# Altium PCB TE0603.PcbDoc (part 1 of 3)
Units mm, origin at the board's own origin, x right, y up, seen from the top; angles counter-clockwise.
Board outline 115 x 70 mm, 4 copper layers (L 01 (Top), L 02, L 03, L 04 (Bot)), stack 1.564 mm thick; 86 components, 166 nets, 587 pads, 211 vias.
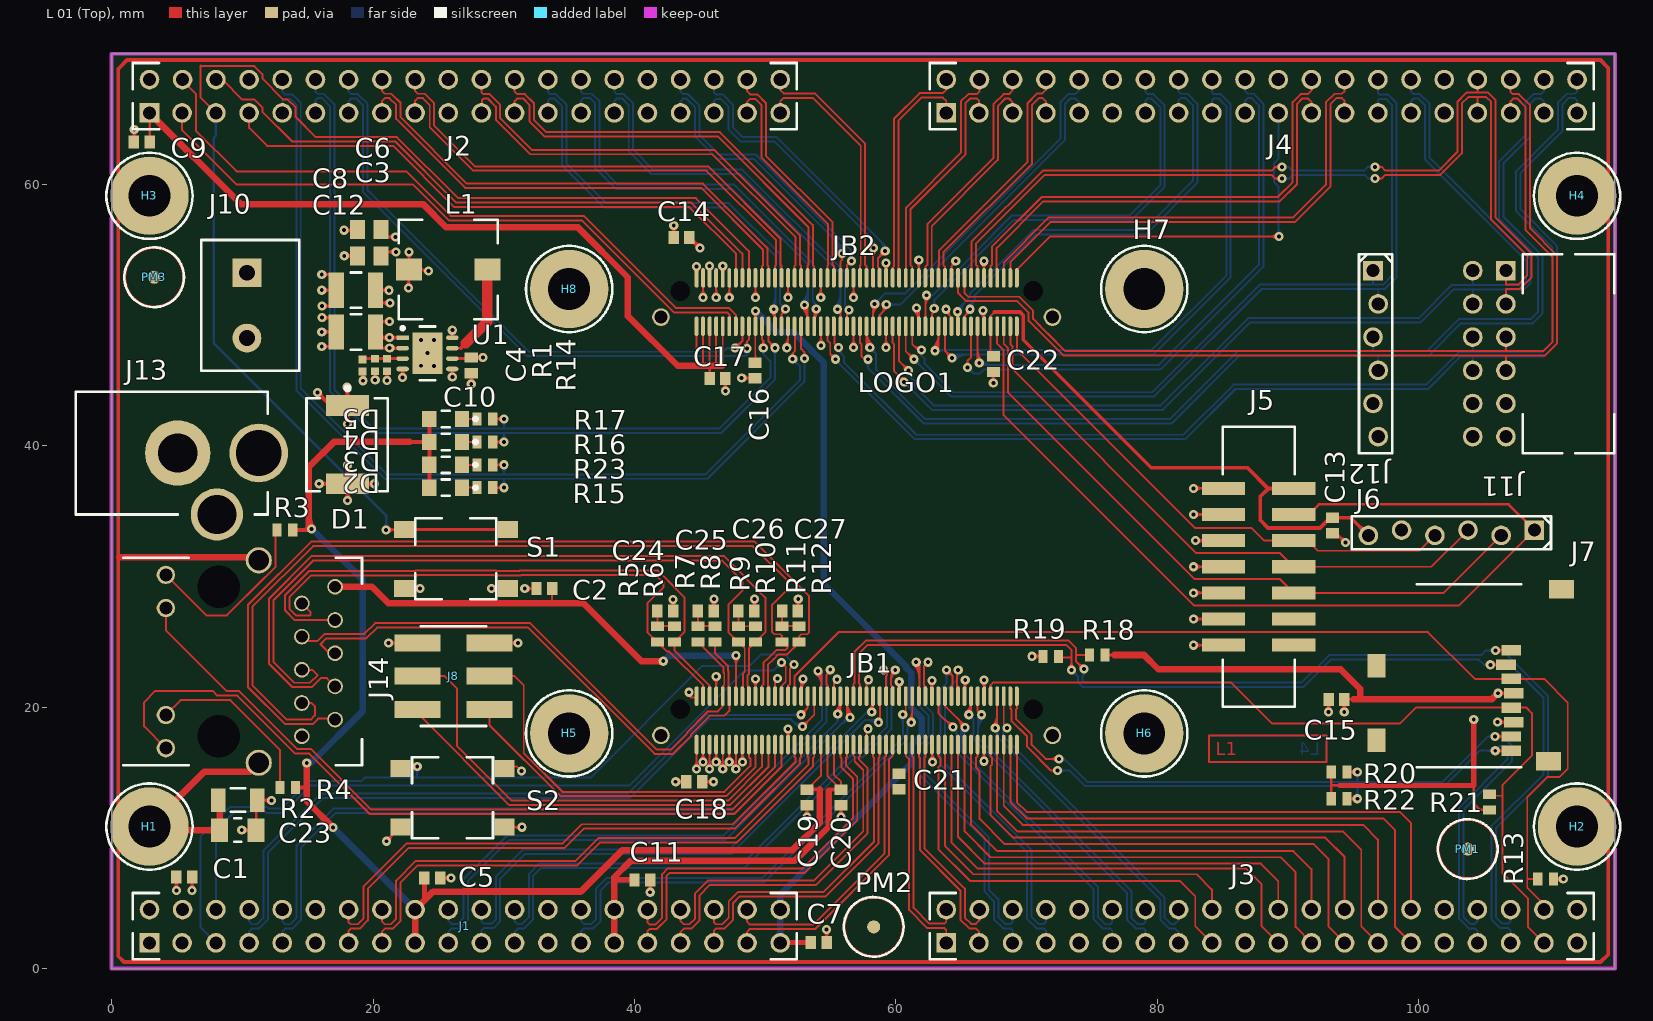
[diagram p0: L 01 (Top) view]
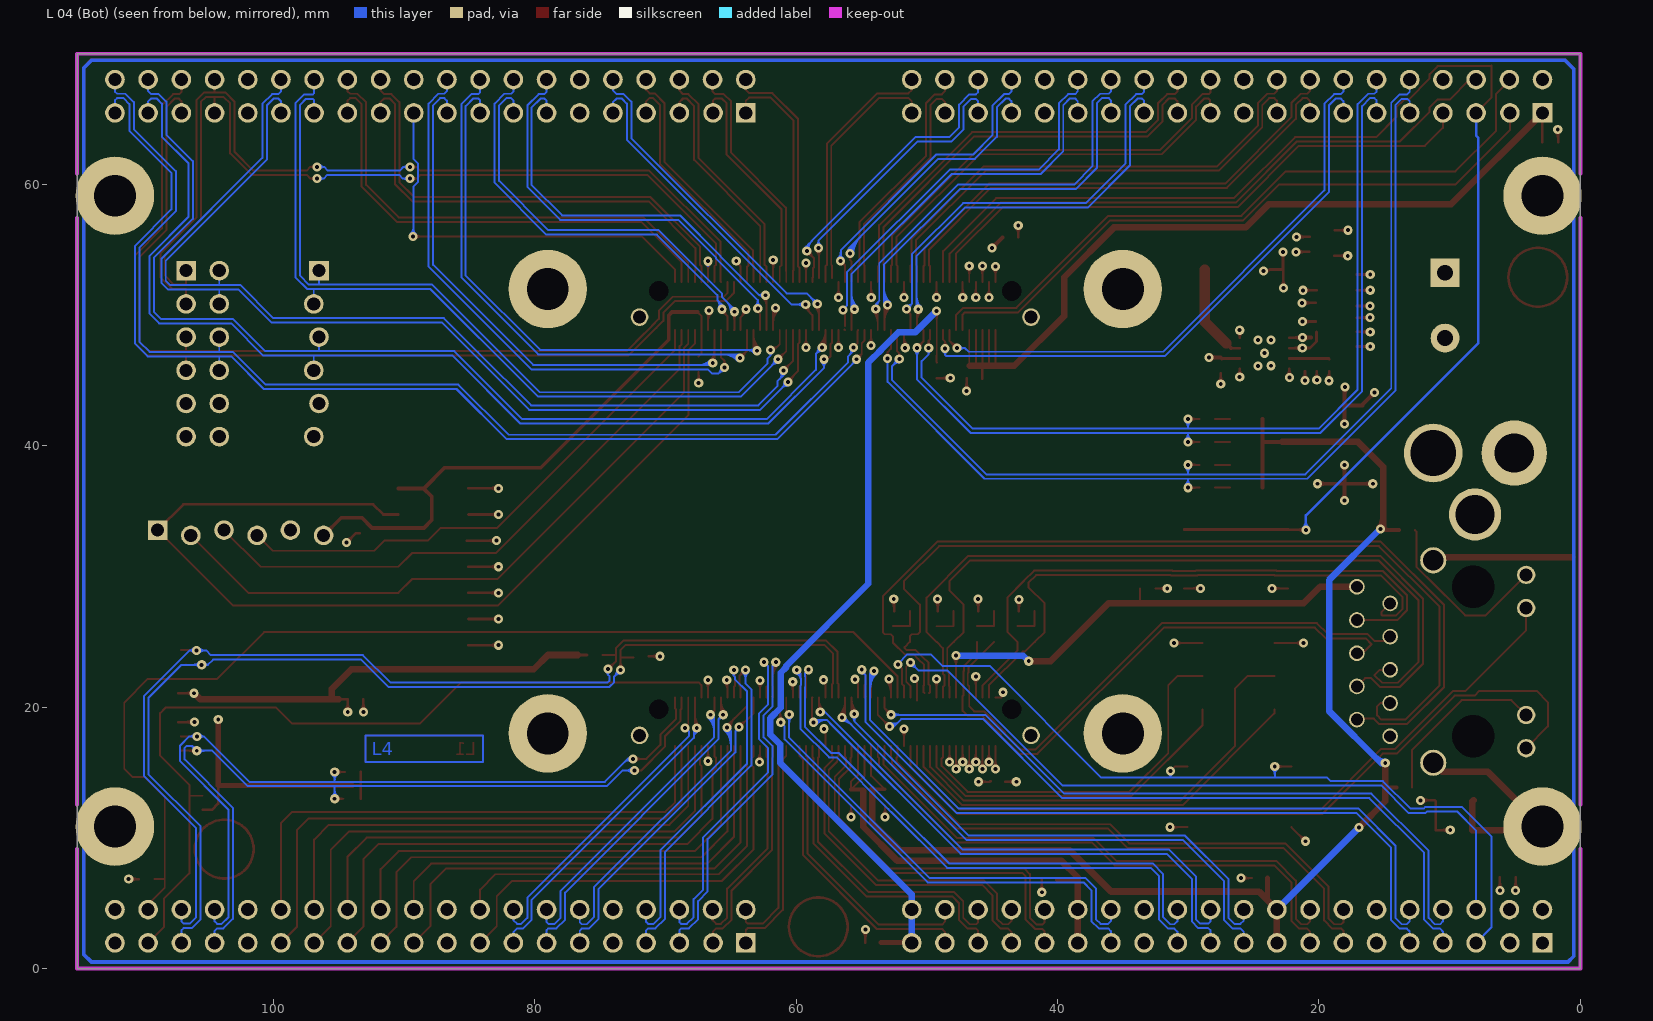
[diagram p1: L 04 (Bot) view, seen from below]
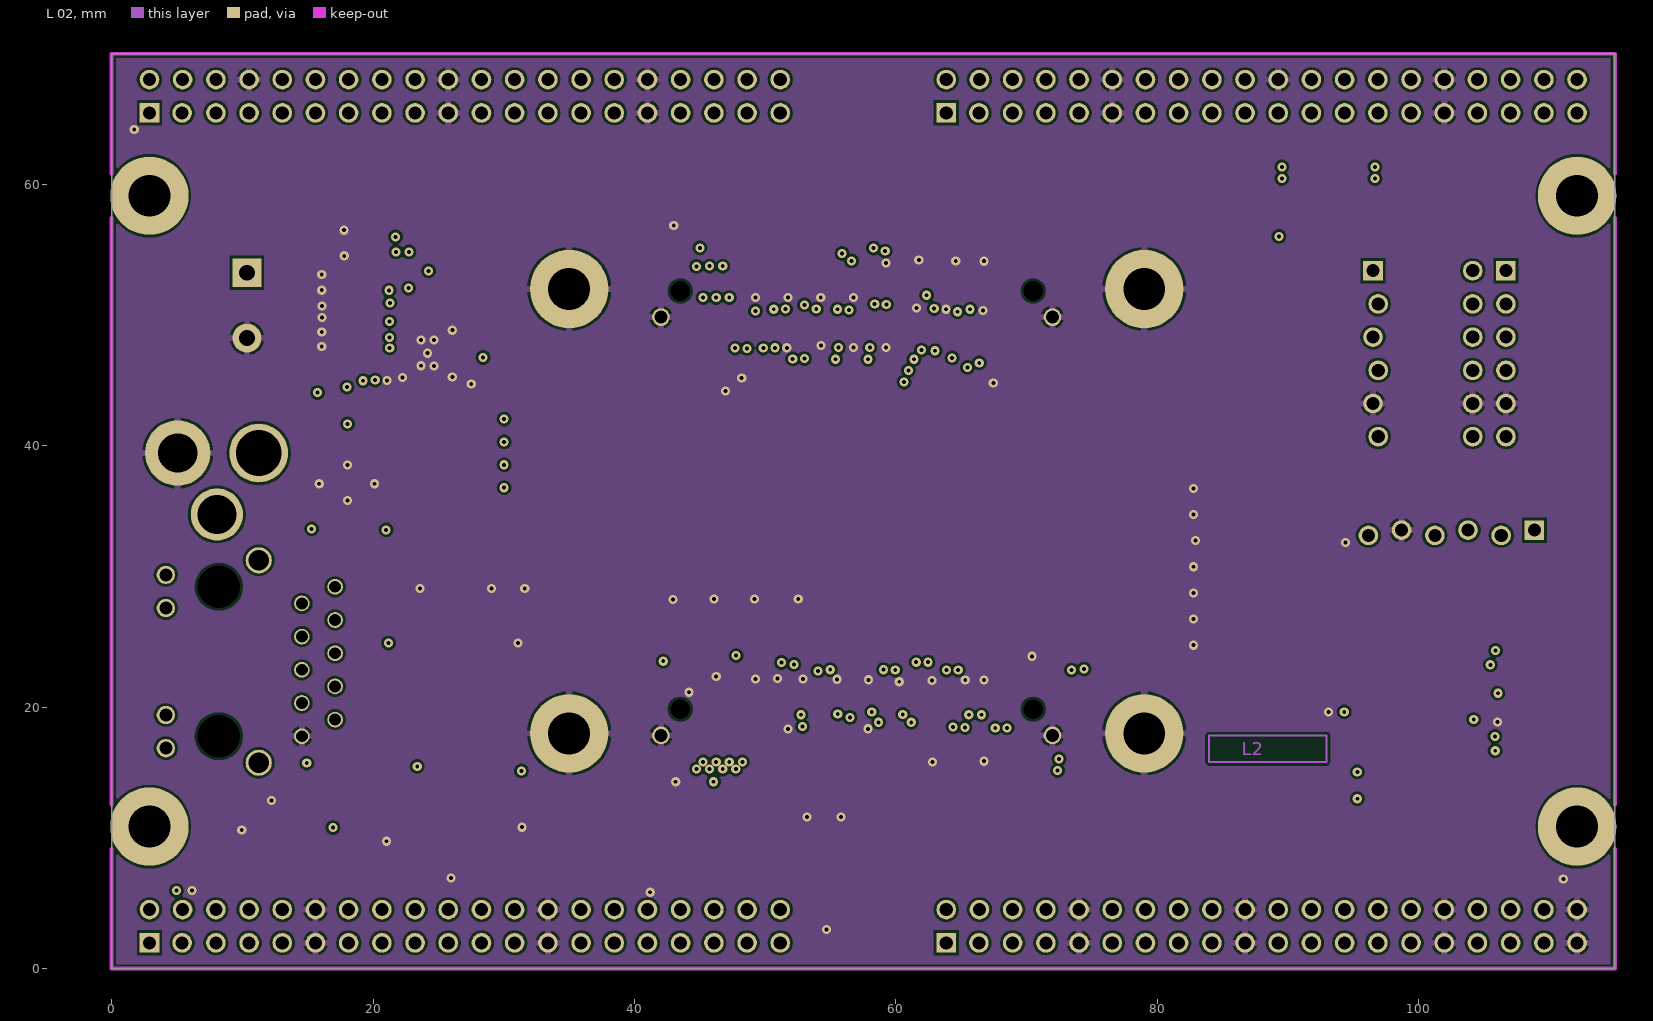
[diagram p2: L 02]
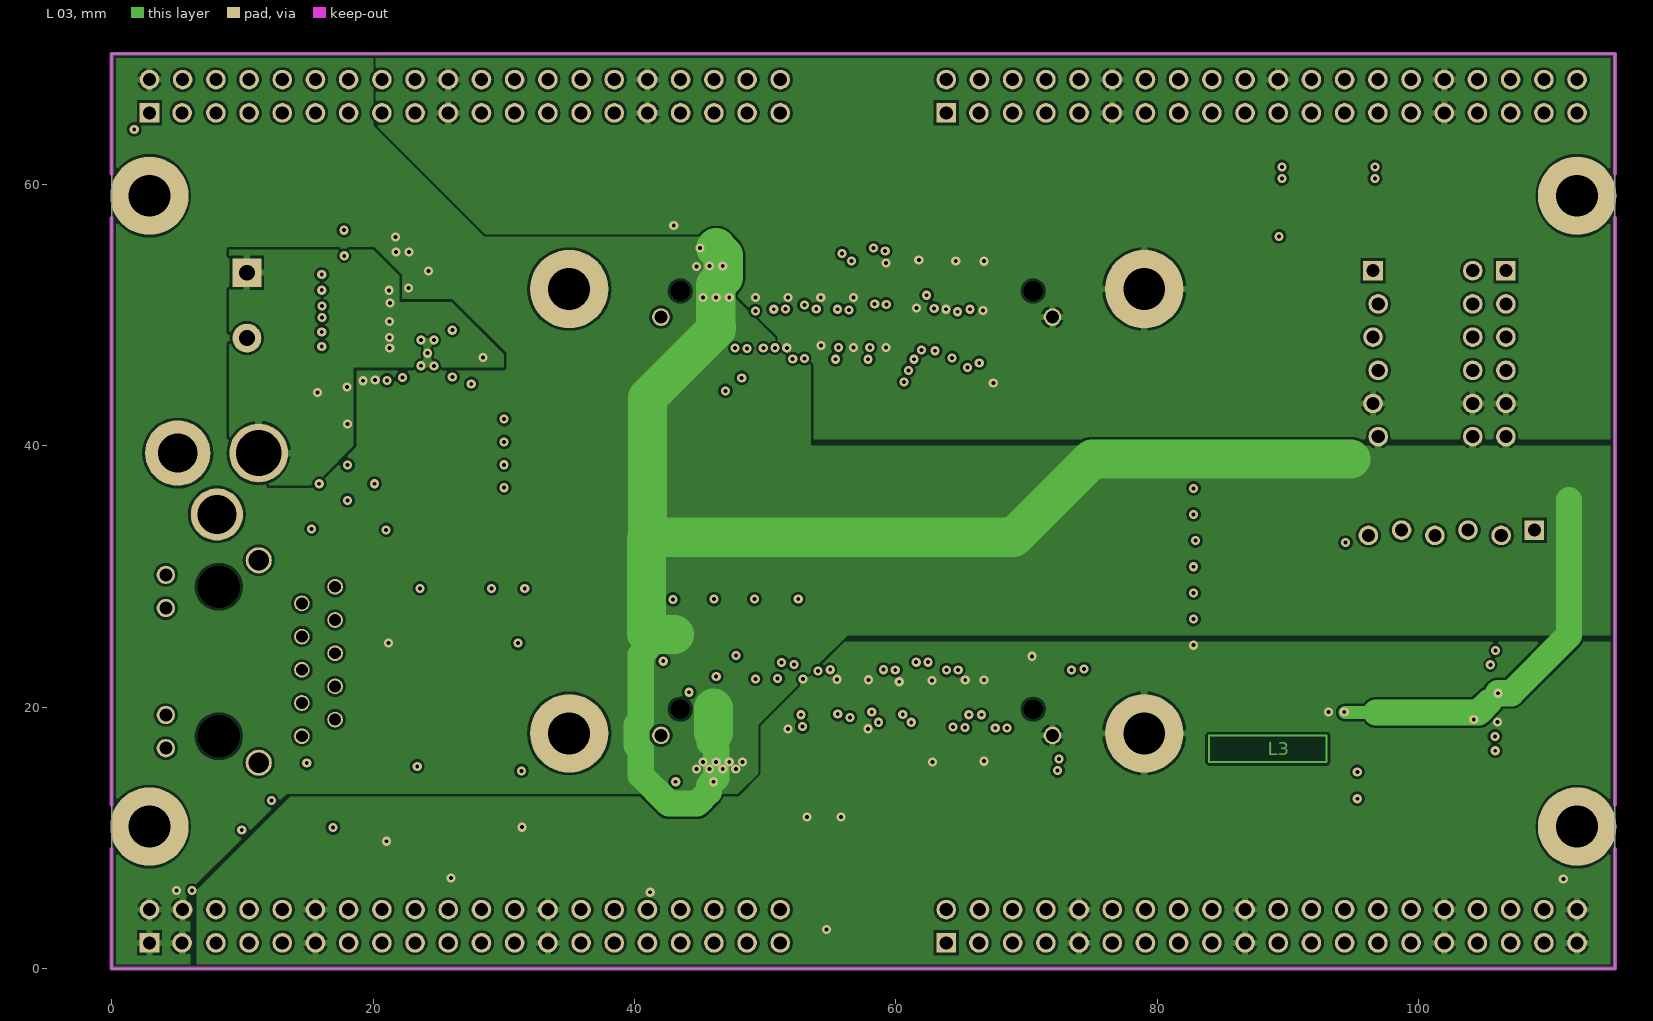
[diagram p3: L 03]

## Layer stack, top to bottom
L 01 (Top): signal copper 0.05
Dielectric: core 0.134, FR-4, Dk 4.8
L 02: signal copper 0.033
Dielectric: prepreg 1.13, FR-4, Dk 4.8
L 03: signal copper 0.033
Dielectric: core 0.134, FR-4, Dk 4.8
L 04 (Bot): signal copper 0.05

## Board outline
0.001,-0.001 0.001,69.999 115.001,69.999 115.001,-0.001

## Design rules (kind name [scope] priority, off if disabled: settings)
Clearance Clearance_Polygon [(InPolygon)] p1: gap=0.2
Clearance [All] p2: gap=0.19
ComponentClearance [All] p1: gap=-0.05 collisioncheckmode=3 verticalgap=0.254 showdistances=FALSE
DiffPairsRouting [All] p1: maxlimit=1 minlimit=0.189 mostfreqgap=1 toplayer_maxgap=0.191 toplayer_prefgap=0.19 midlayer1_mingap=1 midlayer2_mingap=1 bottomlayer_maxgap=0.191 bottomlayer_prefgap=0.19 maxuncoupledlength=20
FabricationTestPointUsage TestPointUsage [All] p1: valid=0 allowmultiple=FALSE
FabricationTestpoint Testpoint [All] p1: side=3 testpointundercomponent=TRUE minsize=1.016 maxsize=2.54 preferedsize=1.524 minholesize=0 maxholesize=1.016 preferedholesize=0.813 testpointgrid=0.025 allowsidetop=TRUE allowsidebottom=TRUE usegrid=TRUE gridtolerance=0
HoleSize [All] p1: absolutevalues=TRUE maxlimit=5 minlimit=0.3 maxpercent=80.000 minpercent=20.000
MinimumAnnularRing [All] p1: minimumring=0.15
PolygonConnect PolygonConnect_Via [IsVia] p1: connectstyle=Direct reliefconductorwidth=0.254 reliefentries=4 polygonreliefangle="90 Angle"
PolygonConnect [All] p2: connectstyle=Relief reliefconductorwidth=0.5 reliefentries=4 polygonreliefangle="90 Angle"
RoutingLayers [All] p1: top layer_v5=TRUE mid layer 1_v5=FALSE mid layer 2_v5=FALSE bottom layer_v5=TRUE
RoutingVias [All] p1: holewidth=0.3 width=0.7 viastyle="Through Hole" minholewidth=0.3 minwidth=0.7 maxholewidth=1 maxwidth=3
SMDNeckDown [All] p1: percent=60.000
SilkToSilkClearance [All] p1: silktosilkclearance=0.1
SilkscreenOverComponentPads [All] p1: minsilkscreentomaskgap=0.1
SolderMaskExpansion SolderMaskExpansion_VIA [(IsVia)] p1: expansion=-10
SolderMaskExpansion [All] p2: expansion=0.102
Width Width_100Ohm [(InNetClass('D100-33'))] p1: maxlimit=0.15 minlimit=0.15 preferedwidth=0.15
Width [All] p2: maxlimit=3 minlimit=0.15 preferedwidth=0.2
20 further rules are at their usual default settings.

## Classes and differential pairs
net class S50-33: B2B_B0_L1 B2B_B1_L59 B2B_B2_L29_N B2B_B2_L31_N B2B_B2_L32_N
net class D100-33: B2B_B0_L2_N B2B_B0_L2_P B2B_B0_L3_N B2B_B0_L3_P B2B_B0_L4_N B2B_B0_L4_P B2B_B0_L5_N B2B_B0_L5_P B2B_B0_L6_N B2B_B0_L6_P B2B_B0_L7_N B2B_B0_L7_P B2B_B0_L8_N B2B_B0_L8_P B2B_B0_L32_N B2B_B0_L32_P B2B_B0_L33_N B2B_B0_L33_P B2B_B0_L34_N B2B_B0_L34_P B2B_B0_L35_N B2B_B0_L35_P B2B_B0_L36_N B2B_B0_L36_P B2B_B0_L37_N B2B_B0_L37_P B2B_B0_L38_N B2B_B0_L38_P B2B_B0_L49_N B2B_B0_L49_P B2B_B0_L50_N B2B_B0_L50_P B2B_B0_L51_N B2B_B0_L51_P B2B_B0_L62_N B2B_B0_L62_P B2B_B0_L63_N B2B_B0_L63_P B2B_B0_L64_N B2B_B0_L64_P B2B_B0_L65_N B2B_B0_L65_P B2B_B0_L66_N B2B_B0_L66_P B2B_B1_L9_N B2B_B1_L9_P B2B_B1_L10_N B2B_B1_L10_P B2B_B1_L19_N B2B_B1_L19_P B2B_B1_L20_N B2B_B1_L20_P B2B_B1_L21_N B2B_B1_L21_P B2B_B1_L61_N B2B_B1_L61_P B2B_B2_L2_N B2B_B2_L2_P B2B_B2_L4_N B2B_B2_L4_P B2B_B2_L5_N B2B_B2_L5_P B2B_B2_L6_N B2B_B2_L6_P B2B_B2_L8_N B2B_B2_L8_P B2B_B2_L9_N B2B_B2_L9_P B2B_B2_L10_N B2B_B2_L10_P B2B_B2_L11_N B2B_B2_L11_P B2B_B2_L15_N B2B_B2_L15_P B2B_B2_L18_N B2B_B2_L18_P B2B_B2_L21_N B2B_B2_L21_P B2B_B2_L41_N B2B_B2_L41_P B2B_B2_L42_N B2B_B2_L42_P B2B_B2_L43_N B2B_B2_L43_P B2B_B2_L44_N B2B_B2_L44_P B2B_B2_L45_N B2B_B2_L45_P B2B_B2_L48_N B2B_B2_L48_P B2B_B2_L49_N B2B_B2_L49_P B2B_B2_L57_N B2B_B2_L57_P B2B_B2_L59_N B2B_B2_L59_P B2B_B2_L60_N B2B_B2_L60_P B2B_B3_L9_N B2B_B3_L9_P B2B_B3_L59_N B2B_B3_L59_P B2B_B3_L60_N B2B_B3_L60_P PHY_MDI0_N PHY_MDI0_P PHY_MDI1_N PHY_MDI1_P PHY_MDI2_N PHY_MDI2_P PHY_MDI3_N PHY_MDI3_P
component class Signals: C14 C16 C17 C18 C19 C20 C21 C22 C23 D1 D2 D3 D4 D5 D? J10 J13 JB1 JB2 R2 R15 R16 R17 R23 S1 S2
component class Connector: C1 C5 C7 C9 C11 C13 C15 J1 J2 J3 J4 J5 J6 J7 J8 J11 J12 R13 R18 R19 R20 R21 R22
component class Main: C3 C4 C6 C8 C10 C12 H1 H2 H3 H4 H5 H6 H7 H8 L1 LOGO1 PM1 PM2 PM3 R1 R14 U1
component class Ethernet: C2 C24 C25 C26 C27 J14 R3 R4 R5 R6 R7 R8 R9 R10 R11 R12
differential pair B2B_B3_L60: +B2B_B3_L60_P -B2B_B3_L60_N
differential pair B2B_B3_L59: +B2B_B3_L59_P -B2B_B3_L59_N
differential pair B2B_B3_L9: +B2B_B3_L9_P -B2B_B3_L9_N
differential pair B2B_B2_L60: +B2B_B2_L60_P -B2B_B2_L60_N
differential pair B2B_B2_L59: +B2B_B2_L59_P -B2B_B2_L59_N
differential pair B2B_B2_L57: +B2B_B2_L57_P -B2B_B2_L57_N
differential pair B2B_B2_L49: +B2B_B2_L49_P -B2B_B2_L49_N
differential pair B2B_B2_L48: +B2B_B2_L48_P -B2B_B2_L48_N
differential pair B2B_B2_L45: +B2B_B2_L45_P -B2B_B2_L45_N
differential pair B2B_B2_L44: +B2B_B2_L44_P -B2B_B2_L44_N
differential pair B2B_B2_L43: +B2B_B2_L43_P -B2B_B2_L43_N
differential pair B2B_B2_L42: +B2B_B2_L42_P -B2B_B2_L42_N
differential pair B2B_B2_L41: +B2B_B2_L41_P -B2B_B2_L41_N
differential pair B2B_B2_L21: +B2B_B2_L21_P -B2B_B2_L21_N
differential pair B2B_B2_L18: +B2B_B2_L18_P -B2B_B2_L18_N
differential pair B2B_B2_L15: +B2B_B2_L15_P -B2B_B2_L15_N
differential pair B2B_B2_L11: +B2B_B2_L11_P -B2B_B2_L11_N
differential pair B2B_B2_L10: +B2B_B2_L10_P -B2B_B2_L10_N
differential pair B2B_B2_L9: +B2B_B2_L9_P -B2B_B2_L9_N
differential pair B2B_B2_L8: +B2B_B2_L8_P -B2B_B2_L8_N
differential pair B2B_B2_L6: +B2B_B2_L6_P -B2B_B2_L6_N
differential pair B2B_B2_L5: +B2B_B2_L5_P -B2B_B2_L5_N
differential pair B2B_B2_L4: +B2B_B2_L4_P -B2B_B2_L4_N
differential pair B2B_B2_L2: +B2B_B2_L2_P -B2B_B2_L2_N
differential pair B2B_B1_L20: +B2B_B1_L20_P -B2B_B1_L20_N
differential pair B2B_B1_L19: +B2B_B1_L19_P -B2B_B1_L19_N
differential pair B2B_B1_L10: +B2B_B1_L10_P -B2B_B1_L10_N
differential pair B2B_B0_L66: +B2B_B0_L66_P -B2B_B0_L66_N
differential pair B2B_B0_L65: +B2B_B0_L65_P -B2B_B0_L65_N
differential pair B2B_B0_L64: +B2B_B0_L64_P -B2B_B0_L64_N
differential pair B2B_B0_L63: +B2B_B0_L63_P -B2B_B0_L63_N
differential pair B2B_B0_L62: +B2B_B0_L62_P -B2B_B0_L62_N
differential pair B2B_B0_L51: +B2B_B0_L51_P -B2B_B0_L51_N
differential pair B2B_B0_L50: +B2B_B0_L50_P -B2B_B0_L50_N
differential pair B2B_B0_L49: +B2B_B0_L49_P -B2B_B0_L49_N
differential pair B2B_B0_L38: +B2B_B0_L38_P -B2B_B0_L38_N
differential pair B2B_B0_L37: +B2B_B0_L37_P -B2B_B0_L37_N
differential pair B2B_B0_L36: +B2B_B0_L36_P -B2B_B0_L36_N
differential pair B2B_B0_L35: +B2B_B0_L35_P -B2B_B0_L35_N
differential pair B2B_B0_L34: +B2B_B0_L34_P -B2B_B0_L34_N
differential pair B2B_B0_L33: +B2B_B0_L33_P -B2B_B0_L33_N
differential pair B2B_B0_L32: +B2B_B0_L32_P -B2B_B0_L32_N
differential pair B2B_B0_L8: +B2B_B0_L8_P -B2B_B0_L8_N
differential pair B2B_B0_L7: +B2B_B0_L7_P -B2B_B0_L7_N
differential pair B2B_B0_L6: +B2B_B0_L6_P -B2B_B0_L6_N
differential pair B2B_B0_L5: +B2B_B0_L5_P -B2B_B0_L5_N
differential pair B2B_B0_L4: +B2B_B0_L4_P -B2B_B0_L4_N
differential pair B2B_B0_L3: +B2B_B0_L3_P -B2B_B0_L3_N
differential pair B2B_B0_L2: +B2B_B0_L2_P -B2B_B0_L2_N
differential pair PHY_MDI0: +PHY_MDI0_P -PHY_MDI0_N
differential pair PHY_MDI1: +PHY_MDI1_P -PHY_MDI1_N
differential pair PHY_MDI2: +PHY_MDI2_P -PHY_MDI2_N
differential pair PHY_MDI3: +PHY_MDI3_P -PHY_MDI3_N
differential pair B2B_B1_L9: +B2B_B1_L9_P -B2B_B1_L9_N
differential pair B2B_B1_L21: +B2B_B1_L21_P -B2B_B1_L21_N
differential pair B2B_B1_L61: +B2B_B1_L61_P -B2B_B1_L61_N

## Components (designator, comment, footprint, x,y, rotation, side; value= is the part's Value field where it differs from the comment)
C1 "100nF" CAPC1608N 5.55,7 r0 top locked
C2 "100nF" CAPC1608N 33.1,29.075 r0 top locked
C3 "10µF" CAPC3225X279N 18.68,51.91 r0 top locked
C4 "4.7nF" CAPC1005X55N 19.2,46.15 r90 top locked
C5 "100nF" CAPC1608N 24.525,6.925 r0 top locked
C6 "22µF" CAPC2012N 19.7,56.55 r180 top locked
C7 "100nF" CAPC1608N 54.1,2 r0 top locked
C8 "22µF" CAPC2012N 19.72,54.54 r180 top locked
C9 "100nF" CAPC1608N 2.3,63.25 r180 top locked
C10 "100nF" CAPC1608N 27.51,46.16 r270 top locked
C11 "100nF" CAPC1608N 40.6,6.8 r0 top locked
C12 "10µF" CAPC3225X279N 18.68,48.71 r0 top locked
C13 "100nF" CAPC1608N 93.4,33.9 r270 top locked
C14 "100nF" CAPC1608N 43.6,55.95 r180 top locked
C15 "10µF" CAPC1608N 93.7,20.6 r180 top locked
C16 "100nF" CAPC1608N 49.225,45.775 r270 top locked
C17 "100nF" CAPC1608N 46.35,45.15 r0 top locked
C18 "100nF" CAPC1608N 44.575,14.3 r0 top locked
C19 "100nF" CAPC1608N 53.2,13.1 r90 top locked
C20 "100nF" CAPC1608N 55.8,13.1 r90 top locked
C21 "100nF" CAPC1608N 60.25,14.325 r90 top
C22 "100nF" CAPC1608N 67.45,46.25 r270 top locked
C23 "100pF" CAPC3216N 9.65,10.6 r0 top locked
C24 "10nF" CAPC1608N 42.35,27.35 r0 top locked
C25 "10nF" CAPC1608N 45.45,27.35 r0 top locked
C26 "10nF" CAPC1608N 48.55,27.35 r0 top locked
C27 "10nF" CAPC1608N 51.9,27.35 r0 top locked
D1 "MBRS340T3" MBRS340T3 18.05,40.1 r90 top locked
D2 "LED Rot 0805" OLD_LED805 25.55,36.8 r0 top
D3 "LED Rot 0805" OLD_LED805 25.55,38.55 r0 top
D4 "LED Rot 0805" OLD_LED805 25.55,40.3 r0 top
D5 "LED Rot 0805" OLD_LED805 25.55,42.05 r0 top
H1 "MHole3.2mm" MHole3_2mm 2.891,10.869 r0 top locked
H2 "MHole3.2mm" MHole3_2mm 112.111,10.869 r0 top locked
H3 "MHole3.2mm" MHole3_2mm 2.891,59.129 r0 top locked
H4 "MHole3.2mm" MHole3_2mm 112.111,59.129 r0 top locked
H5 "MHole3.2mm" MHole3_2mm 35,18 r0 top locked
H6 "MHole3.2mm" MHole3_2mm 79,18 r0 top locked
H7 "MHole3.2mm" MHole3_2mm 79,52 r0 top locked
H8 "MHole3.2mm" MHole3_2mm 35,52 r0 top locked
J1 "STIFTLEISTE2.54 OG 2R-40" "STIFTLEISTE2_54 OG 2R-40" 27.021,3.249 r0 top locked
J2 "STIFTLEISTE2.54 OG 2R-40" "STIFTLEISTE2_54 OG 2R-40" 27.021,66.749 r0 top locked
J3 "STIFTLEISTE2.54 OG 2R-40" "STIFTLEISTE2_54 OG 2R-40" 87.981,3.249 r0 top locked
J4 "STIFTLEISTE2.54 OG 2R-40" "STIFTLEISTE2_54 OG 2R-40" 87.981,66.749 r0 top locked
J5 "WANNE2mm2R-14" WANNE2mm2R-14 87.75,30.75 r270 top locked
J6 "Stiftleiste versetzt 1-reihig, 6pol." "STIFTLEISTE2_54 OG 1R-6V" 102.5,33.35 r180 top locked
J7 "Micro SD Socket" 112A-TXAR-R01 103.85,22.45 r270 top locked
J8 "SMD-254-9132-14-6" SMD-254-9132-14-6 26.15,22.375 r270 top locked
J10 "ARK500-2" ARK500-2 10.35,50.75 r270 top locked
J11 "BUCHSENLEISTE-2.54-12-2R-90" BUCHSENLEISTE-2.54-12-2R-90 105.4,47.05 r270 top
J12 "Stiftleiste versetzt 1-reihig, 6pol." "STIFTLEISTE2_54 OG 1R-6V" 96.7,47.05 r270 top locked
J13 "2.1mm Jack" WS-DC001 11.25,39.45 r0 top locked
J14 "MIC38013-5151T-LF3" MIC38013-5151T-LF3 11.25,23.5 r90 top locked
JB1 "LSHM-150-04.0-L-DV-A-S-K-TR" LSHM-150-XXX-X-DV-A-X 57,19 r180 top locked
JB2 "LSHM-150-04.0-L-DV-A-S-K-TR" LSHM-150-XXX-X-DV-A-X 57,51 r180 top locked
L1 "2.2µH" WE-PD-S-P 25.75,53.49 r90 top locked
LOGO1 "LOGO PRINT" "LOGO PRINT" 54.175,39.325 r0 top
PM1 "FIDU-DOT" FIDU-DOT 103.75,9.15 r0 top locked
PM2 "FIDU-DOT" FIDU-DOT 58.3,3.2 r0 top locked
PM3 "FIDU-DOT" FIDU-DOT 3.25,52.9 r0 top locked
R1 "3K57" RESC1005N 20.16,46.18 r90 top locked
R2 "1M" RESC3216N 9.65,12.9 r0 top locked
R3 "240R" RESC1609N 13.25,33.55 r0 top locked
R4 "240R" RESC1609N 13.475,13.85 r0 top locked
R5 "49R9" RESC1609N 41.75,25.601 r90 top locked
R6 "49R9" RESC1609N 43.05,25.601 r90 top locked
R7 "49R9" RESC1609N 44.85,25.601 r90 top locked
R8 "49R9" RESC1609N 46.15,25.601 r90 top locked
R9 "49R9" RESC1609N 47.95,25.6 r90 top locked
R10 "49R9" RESC1609N 49.25,25.6 r90 top locked
R11 "49R9" RESC1609N 51.3,25.601 r90 top locked
R12 "49R9" RESC1609N 52.6,25.601 r90 top locked
R13 "49R9" RESC1609N 109.7,6.85 r0 top locked
R14 "1K13" RESC1005N 21.06,46.18 r270 top locked
R15 "240R" RESC1609N 28.55,36.8 r0 top locked
R16 "240R" RESC1609N 28.55,40.3 r0 top locked
R17 "240R" RESC1609N 28.55,42.05 r0 top locked
R18 "470K" RESC1609N 71.85,23.9 r0 top locked
R19 "68K" RESC1609N 75.4,24 r180 top locked
R20 "68K" RESC1609N 93.91,15.05 r0 top
R21 "15K" RESC1609N 105.4,12.75 r90 top locked
R22 "68K" RESC1609N 93.91,13 r0 top
R23 "240R" RESC1609N 28.55,38.55 r0 top locked
S1 "KSC241" DTSM61N 26.33,31.35 r0 top locked
S2 "KSC241" DTSM61N 26.075,13.075 r0 top locked
U1 "ST1S10PUR" SON80P400X400X100-9N 24.16,47.08 r0 top locked

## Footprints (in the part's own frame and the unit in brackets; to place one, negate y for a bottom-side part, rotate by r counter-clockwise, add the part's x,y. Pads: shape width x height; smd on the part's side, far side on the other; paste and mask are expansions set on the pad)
112A-TXAR-R01 [mm] "Micro SD Socket"
  rect 0.8x1.5 smd: 1(-1.915,3.225) 2(-0.815,2.825) 3(0.285,3.225) 4(1.385,3.425) 5(2.485,3.225) 6(3.585,3.425) 7(4.685,3.225) 8(5.785,3.225)
  rect 1.4x1.9 smd: 9(-6.575,7.075) 9(6.575,6.075)
  rect 1.8x1.4 smd: 10(-0.725,-7.075) 10(4.975,-7.075)
  silkscreen extent -6.97,-4 7.03,4
ARK500-2 [mm] "AR-Klemmen 250V 2pol. grau"
  rect 2.2x2.2 hole 1.2: 1(-2.5,0)
  round 2.2 hole 1.2: 2(2.5,0)
  silkscreen extent -5,-3.5 5,4
BUCHSENLEISTE-2.54-12-2R-90 [mm]
  rect 1.5x1.5 hole 1: 1(-6.35,1.27)
  round 1.5 hole 1: 2(-6.35,-1.27) 3(-3.81,1.27) 4(-3.81,-1.27) 5(-1.27,1.27) 6(-1.27,-1.27) 7(1.27,1.27) 8(1.27,-1.27) 9(3.81,1.27) 10(3.81,-1.27) 11(6.35,1.27) 12(6.35,-1.27)
  silkscreen extent -7.62,2.57 7.62,9.57
CAPC1005X55N [mm] "Vishay VJ0402 1 x 0.5mm (+/- 0.05), 0.25mm +0.05/-0.1mm Kontakte"
  rect 0.6x0.62 smd: 1(-0.46,0) 2(0.46,0)
  body extent -0.53,-0.28 0.53,0.28, height 0.55
CAPC1608N [mm] "Vishay VJ0603 1.6 x 0.8 (+0.15/-0.1) 0.4 +/- 0,15mm Kontakte"
  rect 0.8x1 smd: 1(-0.6,0) 2(0.6,0)
  body extent -0.87,-0.47 0.87,0.47, height 0.95
CAPC2012N [mm] "Vishay VJ0805 2 x 1.25 +/- 0.15, 0.5 +/- 0,2 Kontakte"
  rect 1.15x1.45 smd: 1(-0.9,0) 2(0.9,0)
  body extent -1.07,-0.7 1.07,0.7, height 1.35
CAPC3216N [mm] "Vishay VJ1206 3.2 x 1.6 (+/- 0.15), 0.4mm - 0.8mm Kontakte"
  rect 1.3x1.8 smd: 1(-1.4,0) 2(1.4,0)
  silkscreen extent -0.25,-0.9 0.25,0.9, body extent -1.7,-0.9 1.7,0.9, height 1.8
CAPC3225X279N [mm] "Chip Capacitor, 2-Leads, Body 3,2x2,5mm, IPC Medium Density"
  rect 1.15x2.7 smd: 1(-1.5,0) 2(1.5,0)
  silkscreen extent -0.4,-1.35 0.4,1.35, body extent -1.7,-1.35 1.7,1.35, height 2.79
DTSM61N [mm] "SMD-Taster"
  rect 1.55x1.3 smd: 1(-3.975,2.25) 1(3.975,2.25) 2(-3.975,-2.25) 2(3.975,-2.25)
  silkscreen extent -3.1,-3.1 3.1,3.1, body extent -3.1,-3.1 3.1,3.1, height 4.5
FIDU-DOT [mm]
  round 1 smd paste-1 mask+2: 0(0,0)
  L 01 (Top) circle w0.2: c0,0 r2.25
  silkscreen extent -2.28,-2.29 2.29,2.29
"LOGO PRINT" [mm]
LSHM-150-XXX-X-DV-A-X [mm]
  oval 0.3x1.5 smd: 1(12.25,-1.85) 2(12.25,1.85) 3(11.75,-1.85) 4(11.75,1.85) 5(11.25,-1.85) 6(11.25,1.85) 7(10.75,-1.85) 8(10.75,1.85) 9(10.25,-1.85) 10(10.25,1.85) 11(9.75,-1.85) 12(9.75,1.85) 13(9.25,-1.85) 14(9.25,1.85) 15(8.75,-1.85) 16(8.75,1.85) 17(8.25,-1.85) 18(8.25,1.85) 19(7.75,-1.85) 20(7.75,1.85) 21(7.25,-1.85) 22(7.25,1.85) 23(6.75,-1.85) 24(6.75,1.85) 25(6.25,-1.85) 26(6.25,1.85) 27(5.75,-1.85) 28(5.75,1.85) 29(5.25,-1.85) 30(5.25,1.85) 31(4.75,-1.85) 32(4.75,1.85) 33(4.25,-1.85) 34(4.25,1.85) 35(3.75,-1.85) 36(3.75,1.85) 37(3.25,-1.85) 38(3.25,1.85) 39(2.75,-1.85) 40(2.75,1.85) 41(2.25,-1.85) 42(2.25,1.85) 43(1.75,-1.85) 44(1.75,1.85) 45(1.25,-1.85) 46(1.25,1.85) 47(0.75,-1.85) 48(0.75,1.85) 49(0.25,-1.85) 50(0.25,1.85) 51(-0.25,-1.85) 52(-0.25,1.85) 53(-0.75,-1.85) 54(-0.75,1.85) 55(-1.25,-1.85) 56(-1.25,1.85) 57(-1.75,-1.85) 58(-1.75,1.85) 59(-2.25,-1.85) 60(-2.25,1.85) 61(-2.75,-1.85) 62(-2.75,1.85) 63(-3.25,-1.85) 64(-3.25,1.85) 65(-3.75,-1.85) 66(-3.75,1.85) 67(-4.25,-1.85) 68(-4.25,1.85) 69(-4.75,-1.85) 70(-4.75,1.85) 71(-5.25,-1.85) 72(-5.25,1.85) 73(-5.75,-1.85) 74(-5.75,1.85) 75(-6.25,-1.85) 76(-6.25,1.85) 77(-6.75,-1.85) 78(-6.75,1.85) 79(-7.25,-1.85) 80(-7.25,1.85) 81(-7.75,-1.85) 82(-7.75,1.85) 83(-8.25,-1.85) 84(-8.25,1.85) 85(-8.75,-1.85) 86(-8.75,1.85) 87(-9.25,-1.85) 88(-9.25,1.85) 89(-9.75,-1.85) 90(-9.75,1.85) 91(-10.25,-1.85) 92(-10.25,1.85) 93(-10.75,-1.85) 94(-10.75,1.85) 95(-11.25,-1.85) 96(-11.25,1.85) 97(-11.75,-1.85) 98(-11.75,1.85) 99(-12.25,-1.85) 100(-12.25,1.85)
  round 1.35 hole 1: F1(14.975,1.15) F2(-14.975,1.15)
  round 0 hole 1.5 unplated mask+0.75: H1(13.5,-0.85) H2(-13.5,-0.85)
  body extent -15.4,-2.49 15.4,2.64, height 3.95
MBRS340T3 [mm]
  rect 1.6x3.27 smd: 1(3,0) 2(-3,0)
  silkscreen extent -3.56,-3.07 4.45,3.15
MHole3_2mm [mm]
  round 6 hole 3.2: 1(0,0)
  silkscreen extent -3.3,-3.3 3.3,3.3
MIC38013-5151T-LF3 [mm]
  round 1.2 hole 0.9: 1(5.715,-5.84) 2(4.445,-3.3) 3(3.175,-5.84) 4(1.905,-3.3) 5(0.635,-5.84) 6(-0.635,-3.3) 7(-1.905,-5.84) 8(-3.175,-3.3) 9(-4.445,-5.84) 10(-5.715,-3.3)
  round 1.4 hole 1: 11(6.63,7.11) 12(4.09,7.11) 13(-4.09,7.11) 14(-6.63,7.11)
  round 2 hole 1.6: 15(7.745,0) 16(-7.745,0)
  round 0 hole 3.25 unplated: H1(5.715,3.05) H2(-5.715,3.05)
  silkscreen extent -7.94,-7.9 7.94,10.36, body extent -7.94,-7.9 7.94,13.94, height 13.74
OLD_LED805 [mm]
  rect 1.1x1.25 smd: A(-1.25,0) K(1.25,0)
  silkscreen extent -0.3,-0.63 2.3,0.63, body extent -1,-0.63 1,0.63, height 1.1
RESC1005N [mm] "Vishay D0402 1 x 0.5mm (+/- 0.05), 0.2mm +/-0.1mm Kontakte"
  rect 0.57x0.62 smd: 1(-0.48,0) 2(0.48,0)
  body extent -0.52,-0.27 0.52,0.27, height 0.4
RESC1609N [mm] "Vishay D0603 1.55 x 0.85 (+0.1/-0.05) 0.3 +/- 0,2mm Kontakte"
  rect 0.7x1 smd: 1(-0.6,0) 2(0.6,0)
  body extent -0.82,-0.47 0.82,0.47, height 0.5
RESC3216N [mm] "Vishay D1206 3.2 x 1.6 (+/- 0.15), 0.2mm - 0.6mm Kontakte"
  rect 1.1x1.8 smd: 1(-1.5,0) 2(1.5,0)
  silkscreen extent -0.55,-0.9 0.55,0.9, body extent -1.65,-0.87 1.65,0.87, height 0.6
SMD-254-9132-14-6 [mm]
  rect 1.3x3.5 smd: 1(-2.54,-2.75) 2(-2.54,2.75) 3(0,-2.75) 4(0,2.75) 5(2.54,-2.75) 6(2.54,2.75)
  silkscreen extent -3.81,-2.5 3.81,2.5
SON80P400X400X100-9N [mm]
  rect 0.95x0.35 smd: 1(-1.9,1.2)
  oval 0.95x0.35 smd: 2(-1.9,0.4) 3(-1.9,-0.4) 4(-1.9,-1.2) 5(1.9,-1.2) 6(1.9,-0.4) 7(1.9,0.4) 8(1.9,1.2)
  rect 2.3x3.2 smd: 9(0,0)
  silkscreen extent -2.02,-2.05 0.6,2.05, body extent -2.05,-2.05 2.05,2.05, height 1
"STIFTLEISTE2_54 OG 1R-6V" [mm]
  rect 1.5x1.5 hole 1: 1(-6.35,-0.2)
  round 1.5 hole 1: 2(-3.81,0.2) 3(-1.27,-0.2) 4(1.27,0.2) 5(3.81,-0.2) 6(6.35,0.2)
  silkscreen extent -7.62,-1.27 7.62,1.27
"STIFTLEISTE2_54 OG 2R-40" [mm]
  rect 1.5x1.5 hole 1: 1(-24.13,-1.27)
  round 1.5 hole 1: 2(-24.13,1.27) 3(-21.63,-1.27) 4(-21.59,1.27) 5(-19.05,-1.27) 6(-19.05,1.27) 7(-16.51,-1.27) 8(-16.51,1.27) 9(-13.97,-1.27) 10(-13.97,1.27) 11(-11.43,-1.27) 12(-11.43,1.27) 13(-8.89,-1.27) 14(-8.89,1.27) 15(-6.35,-1.27) 16(-6.35,1.27) 17(-3.81,-1.27) 18(-3.81,1.27) 19(-1.27,-1.27) 20(-1.27,1.27) 21(1.27,-1.27) 22(1.27,1.27) 23(3.81,-1.27) 24(3.81,1.27) 25(6.35,-1.27) 26(6.35,1.27) 27(8.89,-1.27) 28(8.89,1.27) 29(11.43,-1.27) 30(11.43,1.27) 31(13.97,-1.27) 32(13.97,1.27) 33(16.51,-1.27) 34(16.51,1.27) 35(19.05,-1.27) 36(19.05,1.27) 37(21.59,-1.27) 38(21.59,1.27) 39(24.13,-1.27) 40(24.13,1.27)
  silkscreen extent -25.4,-2.54 25.4,2.54, body extent -25.4,-2.54 25.4,2.54, height 11.3
WANNE2mm2R-14 [mm]
  rect 1x3.3 smd: 1(-6,-2.685) 2(-6,2.685) 3(-4,-2.685) 4(-4,2.685) 5(-2,-2.685) 6(-2,2.685) 7(0,-2.685) 8(0,2.685) 9(2,-2.685) 10(2,2.685) 11(4,-2.685) 12(4,2.685) 13(6,-2.685) 14(6,2.685)
  silkscreen extent -10.7,-2.75 10.7,2.75
WE-PD-S-P [mm]
  rect 1.7x2 smd: 1(0,-3) 2(0,3)
  silkscreen extent -3.8,-3.8 3.8,3.8, body extent -3.8,-3.8 3.8,3.8, height 3.5
WS-DC001 [mm]
  round 4.5 hole 3.5: 1(0,0)
  round 4 hole 3: 2(-3.2,-4.7)
  round 5 hole 3: 3(-6.2,0)
  silkscreen extent -14,-4.7 0.7,4.7

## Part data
C1 C2 C5 C7 C9 C10 C11 C13 C14 C16 C17 C18 C19 C20 C21 C22: library part 21382, "KON 100nF 50V X7R SMD"
C3 C12: library part 23514, "KON 10µF 50V  X5R SMD"
C4: library part 22582, "KON 4,7nF 50V X7R SMD"
C6 C8: library part 23410, "KON 22µF 6,3V  X5R SMD"
C15: library part 22918, "KON 10µF 6,3V X7R SMD"
C23: library part 22679, "KON 100pF X7R"
C24 C25 C26 C27: library part 23774, "KON 10nF 50V X7R SMD"
D1: library part 22887, "MBRS340T3 SMD"
D2 D3 D4 D5: library part 24266, "LED Rot BL-HE135A-AV-TRB SMD obsolete"
H1 H2 H3 H4 H5 H6 H7 H8: library part 22898
J1 J2 J3 J4: library part 22320, "Stiftleiste gerade 2-reihig, 40pol"
J5: library part 22744, "Stiftleiste Wanne 14polig SMD"
J6 J12: library part 22911
J7: library part 23193
J8: library part 22742, "Stiftleiste gerade 2reihig, 6pol. SMD"
J10: library part 20123, "Schraubklemme LP 2 pol ARK500-2"
J11: library part 23185, "Buchsenleiste 2-reihig, 12pol 90°"
J13: library part 22832, "STE 2,1mm Buchse"
J14: library part 23772
JB1 JB2: library part 23838, "STE B2B 100 Pol. 0,5mm 4,0mm"
L1: library part 22681, "IND SMD 2,2µH IDC=4,02A, Isat=4,8A"
LOGO1: library part 23748
PM1 PM2 PM3: library part 22906
R1: library part 23145, "WID SMD 3K57 1% 0,063W"
R2: library part 22757, "WID SMD 1M"
R3 R4 R15 R16 R17 R23: library part 23598, "WID SMD 240R 1% 0,1W"
R5 R6 R7 R8 R9 R10 R11 R12 R13: library part 22534, "WID SMD 49R9 1% 0,1W"
R14: library part 23160, "WID SMD 1K13 1% 0,063W"
R18: library part 21523, "WID SMD 470K 1% 0,1W"
R19 R20 R22: library part 22531, "WID SMD 68K 1% 0,1W"
R21: library part 22528, "WID SMD 15K 1% 0,1W"
S1 S2: library part 24277, "Taster Miniatur Leiterplatte 3N"
U1: library part 23402

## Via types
v1: diameter 0.7, hole 0.3, L 01 (Top) to L 04 (Bot), 211 vias

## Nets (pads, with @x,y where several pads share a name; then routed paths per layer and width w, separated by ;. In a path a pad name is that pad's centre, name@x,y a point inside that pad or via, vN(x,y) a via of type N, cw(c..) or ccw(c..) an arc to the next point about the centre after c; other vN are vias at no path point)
1.2V: C11.1 C20.2 J1.29 J1.30 JB1.42 JB1.44 | length 35.5
  L 01 (Top) w0.15: JB1.42@54.75,17.05 54.75,14.75 C20.2@55.8,13.7 55.8,14.3 55.25,14.85 JB1.44@55.25,17.05
  L 01 (Top) w0.3: 54.86,13.6 54.96,13.7 C20.2@55.8,13.7
  L 01 (Top) w0.4: 38.651,6.8 C11.1@40,6.8
  L 01 (Top) w0.5: J1.29@38.451,1.979 J1.30@38.451,4.519 38.451,7.001 39.725,8.275 52.275,8.275 54.86,10.86 54.86,13.6
1.5V: C7.1 C16.1 J1.39 J1.40 JB2.20 | length 66.1
  L 01 (Top) w0.15: v1@49.056,50.131 cw(c48.616,49.691) JB2.20@49.237,49.691 ; C16.1@49.225,46.375 49.25,46.4 49.25,46.93 49.237,46.943 49.237,48.837 49.237,50.312 v1(49.25,50.325) ; JB2.20@49.237,49.631 cw(c49.944,49.631) v1@49.444,50.131
  L 01 (Top) w0.4: J1.39@51.171,2 C7.1@53.5,2
  L 01 (Top) w0.5: J1.39@51.151,1.979 J1.39@51.171,2
  L 04 (Bot) w0.5: v1(49.25,50.325) 50.9,48.675 52.175,48.675 53.46,47.39 53.46,47.378 53.978,46.86 53.99,46.86 54.475,46.375 54.475,29.442 60.74,23.177 ; J1.39@51.151,1.979 J1.40@51.151,4.519 51.151,5.676 60.251,14.776 61.225,15.75 61.225,17.166 61.965,17.906 61.965,19.177 61.175,19.967 61.175,22.642 60.74,23.077
2.5V: C5.1 C19.2 D2.A D3.A D4.A D5.A J1.17 J1.18 JB1.40 R3.2 R4.2 | length 115
  L 01 (Top) w0.15: C19.2@53.2,13.7 53.23,13.73 54.25,14.75 JB1.40@54.25,17.05
  L 01 (Top) w0.3: R3.2@13.85,33.55 15.2,33.55 v1(15.3,33.65) ; R4.2@14.075,13.85 14.85,13.85 14.888,13.888 14.925,13.888 ; 14.576,33.55 ccw(c14.576,34.374) v1@15.159,33.791 ; 22.8,40.3 D4.A@24.3,40.3 ; D2.A@24.3,36.8 D3.A@24.3,38.55 D4.A@24.3,40.3 ; D5.A@24.3,42.05 D4.A@24.3,40.3 ; C19.2@53.23,13.73 54.17,13.73
  L 01 (Top) w0.4: 23.925,5.234 C5.1@23.925,6.925 ; 26.975,5.975 35.975,5.975
  L 01 (Top) w0.5: v1(14.925,15.725) 14.925,13.888 14.925,12.805 v1(16.93,10.8) ; 15.085,34.41 ccw(c16.06,34.41) v1@15.371,33.721 ; v1(15.3,33.65) 15.085,33.865 15.085,38.385 17,40.3 22.8,40.3 ; J1.17@23.211,1.979 J1.18@23.211,4.519 23.925,5.234 24.591,5.9 35.9,5.9 35.975,5.975 39.05,9.05 52.05,9.05 54.17,11.17 54.17,13.73
  L 04 (Bot) w0.5: v1(14.925,15.725) 15.231,15.725 19.22,19.714 19.22,29.73 v1(15.3,33.65) ; v1@14.925,15.825 ccw(c14.925,16.805) 15.618,16.112 ; v1(16.93,10.8) J1.18@23.211,4.519
3.3V: C1.1 C4.1 C6.1 C8.1 C14.1 C15.1 C18.2 J1.1 J1.2 J1.3 J1.4 J2.2 J7.4 J8.1 J11.11 J11.12 J12.6 JB1.2 JB1.4 JB1.6 JB1.8 JB1.10 JB1.12 JB1.14 JB1.16 JB2.1 JB2.3 JB2.5 JB2.7 JB2.9 JB2.11 L1.2 R1.1 R19.1 R20.1 R21.1 R22.1 | length 273.4
  L 01 (Top) w0.15: v1(21.185,24.915) J8.1@23.4,24.915 ; v1@21.379,24.721 cw(c21.849,24.251) 21.849,24.915 cw(c21.849,25.579) v1@21.379,25.109 ; v1@44.556,15.47 ccw(c44.086,15.939) 44.75,15.939 ccw(c45.414,15.939) v1@44.945,15.47 ; v1@44.556,53.53 cw(c44.086,53.061) 44.75,53.061 cw(c45.414,53.061) v1@44.945,53.53 ; v1(44.75,15.275) JB1.2@44.75,17.05 ; JB2.1@44.75,52.55 v1(44.75,53.725) ; v1@45.056,16.019 ccw(c44.585,16.49) 45.25,16.49 ccw(c45.913,16.488) v1@45.444,16.019 ; v1@45.056,51.545 ccw(c44.586,52.014) 45.25,52.014 ccw(c45.914,52.014) v1@45.445,51.545 ; C18.2@45.175,14.3 v1(46.05,14.3) ; v1(45.25,15.825) JB1.4@45.25,17.05 ; v1(45.25,51.35) JB2.3@45.25,52.55 ; v1@45.556,15.47 ccw(c45.086,15.939) 45.75,15.939 ccw(c46.414,15.939) v1@45.945,15.47 ; v1@45.556,53.555 cw(c45.086,53.086) 45.75,53.086 cw(c46.414,53.086) v1@45.945,53.555 ; v1(45.75,15.275) JB1.6@45.75,17.05 ; JB2.5@45.75,52.55 v1(45.75,53.75) ; v1@45.856,14.106 ccw(c45.386,13.636) 45.386,14.3 ccw(c45.386,14.964) v1@45.856,14.494 ; v1@46.056,16.019 ccw(c45.585,16.49) 46.25,16.49 ccw(c46.913,16.488) v1@46.444,16.019 ; v1@46.056,51.545 ccw(c45.586,52.014) 46.25,52.014 ccw(c46.914,52.014) v1@46.445,51.545 ; v1(46.25,15.825) JB1.8@46.25,17.05 ; v1(46.25,51.35) JB2.7@46.25,52.55 ; v1@46.556,15.47 ccw(c46.086,15.939) 46.75,15.939 ccw(c47.414,15.939) v1@46.945,15.47 ; v1@46.556,53.555 cw(c46.086,53.086) 46.75,53.086 cw(c47.414,53.086) v1@46.945,53.555 ; v1(46.75,15.275) JB1.10@46.75,17.05 ; JB2.9@46.75,52.55 v1(46.75,53.75) ; v1@47.056,16.019 ccw(c46.585,16.49) 47.25,16.49 ccw(c47.913,16.488) v1@47.444,16.019 ; v1@47.056,51.545 ccw(c46.586,52.014) 47.25,52.014 ccw(c47.914,52.014) v1@47.445,51.545 ; v1(47.25,15.825) JB1.12@47.25,17.05 ; v1(47.25,51.35) JB2.11@47.25,52.55 ; v1@47.556,15.47 ccw(c47.086,15.939) 47.75,15.939 ccw(c48.414,15.939) v1@47.945,15.47 ; v1(47.75,15.275) JB1.14@47.75,17.05 ; v1@48.056,16.019 ccw(c47.585,16.49) 48.25,16.49 ccw(c48.913,16.488) v1@48.444,16.019 ; v1(48.25,15.825) JB1.16@48.25,17.05
  L 01 (Top) w0.2: v1@4.773,6.152 ccw(c4.346,6.579) 4.95,6.579 ccw(c5.554,6.579) v1@5.127,6.152 ; v1(4.95,5.975) C1.1@4.95,7 ; v1@19.063,45.157 ccw(c18.709,45.511) C4.1@19.21,45.511 ; C4.1@19.21,45.656 ccw(c19.916,45.656) v1@19.417,45.157 ; C4.1@19.21,45.72 19.21,45.01 v1(19.24,44.98) ; v1@19.983,45.207 ccw(c19.556,45.634) 20.16,45.634 ccw(c20.764,45.634) v1@20.337,45.207 ; v1(20.16,45.03) R1.1@20.16,45.7 ; C6.1@20.69,55.99 v1(21.72,55.99) ; C8.1@20.73,54.84 v1(21.76,54.84) ; v1@21.543,55.813 ccw(c21.116,55.386) 21.116,55.99 ccw(c21.116,56.594) v1@21.543,56.167 ; v1@21.583,54.663 ccw(c21.156,54.236) 21.156,54.84 ccw(c21.156,55.444) v1@21.583,55.017 ; v1@22.533,52.247 ccw(c22.058,52.722) L1.2@22.73,52.722 ; v1@22.563,54.663 cw(c22.112,54.212) L1.2@22.75,54.212 ; v1@22.73,52.38 L1.2@22.73,53.41 ; 22.73,52.625 ccw(c23.265,52.625) v1@22.887,52.247 ; v1(22.74,54.84) 22.74,54.53 22.75,54.52 L1.2@22.75,53.49 23.78,53.49 23.88,53.39 ; L1.2@22.75,54.261 cw(c23.319,54.261) v1@22.917,54.663 ; v1@24.006,53.303 ccw(c23.88,53.256) 23.88,53.39 ; v1@24.006,53.477 cw(c23.88,53.524) 23.88,53.39 ; v1(24.24,53.39) 23.88,53.39 ; R19.1@76,24 76.71,24 ; R22.1@93.31,13 93.31,14.02 ; R20.1@93.31,15.05 93.31,14.02 ; v1@94.123,19.827 ccw(c93.696,20.254) 94.3,20.254 ccw(c94.904,20.254) v1@94.477,19.827 ; v1(94.3,19.65) C15.1@94.3,20.6 94.99,20.6 ; v1@104.033,18.883 cw(c103.606,18.456) 104.21,18.456 cw(c104.814,18.456) v1@104.387,18.883 ; 104.205,14.02 93.93,14.02 93.31,14.02 ; v1(104.21,19.06) 104.21,12.63 104.69,12.15 R21.1@105.4,12.15 ; v1@106.06,21.065 J7.4@107.275,21.065 ; v1@106.227,20.898 cw(c106.629,20.496) J7.4@106.629,21.065 ; v1@106.227,21.252 ccw(c106.678,21.703) J7.4@106.678,21.065
  L 01 (Top) w0.3: C14.1@44.2,55.95 v1(45,55.15) ; v1@44.8,55.15 ccw(c44.317,55.15) 44.659,55.491 ccw(c45,55.833) v1@45,55.35
  L 01 (Top) w0.4: 93.93,14.02 104.21,14.02 v1(104.21,19.06)
  L 01 (Top) w0.5: 76.71,24 78.98,24 80.07,22.91 94.015,22.91 95.51,21.415 95.51,20.6 ; 94.99,20.6 95.51,20.6 ; v1(106.05,21.075) 105.575,20.6 95.51,20.6
  L 03 w1: v1@94.35,19.6 96,19.6
  L 03 w2: 40.91,25.64 40.91,24.413 40.475,23.978 40.475,18.938 40.16,18.623 40.16,17.077 40.475,16.762 40.475,14.797 42.637,12.635 44.788,12.635 45.69,13.537 45.69,14.015 46.25,14.575 v1(46.25,15.825) 46.25,16.825 45.75,17.325 ; 96.75,19.6 104.572,19.6 105.387,20.415 ; v1(106.05,21.075) 107.075,21.075 111.5,25.5 111.5,35.87
  L 03 w3: 43.045,25.565 40.985,25.565 40.91,25.64 40.91,32.91 41,33 ; 46.04,18.072 46.04,19.928 ; 46.25,55.15 46.25,55.11 46.79,54.57 46.79,52.88 46.21,52.3 46.21,49.205 46.25,49.165 46.25,48.935 41,43.685 41,33 ; 94.79,39 75,39 69,33 41,33
  L 04 (Bot) w0.15: v1@21.175,24.925 v1(21.185,24.915)
  other v1: 22.71,52.07
/MR: J2.5 JB2.17 S1.1 | length 103.6
  L 01 (Top) w0.15: J2.5@7.971,65.479 6.781,66.67 6.781,69.094 6.825,69.05 10.916,69.05 11.526,68.44 11.526,68.109 13.14,66.494 13.471,66.494 14.066,65.9 14.066,65.159 15.6,63.625 21.825,63.625 26.5,58.95 44.7,58.95 48.75,54.9 JB2.17@48.75,52.55
  L 01 (Top) w0.2: v1(21,33.575) 22.33,33.575 S1.1@22.355,33.6 S1.1@30.305,33.6 ; v1@21.177,33.398 cw(c21.604,32.971) 21.604,33.575 cw(c21.604,34.179) v1@21.177,33.752
  L 04 (Bot) w0.2: J2.5@7.971,65.479 7.971,63.729 7.82,63.579 7.82,47.85 21,34.67 v1(21,33.575) ; v1@20.823,33.752 ccw(c20.396,34.179) 21,34.179 ccw(c21.604,34.179) v1@21.177,33.752
AWAKE: J3.24 JB1.86 | length 36.6
  L 01 (Top) w0.15: JB1.86@65.75,17.05 65.75,11.008 67.758,9 90.4,9 91.791,7.609 J3.24@91.791,4.519
B2B_B0_L1: J2.7 JB2.13 | length 44.5
  L 01 (Top) w0.15: J2.7@10.511,65.479 10.511,64.329 11.895,62.945 21.543,62.945 26.218,58.27 44.205,58.27 47.75,54.725 JB2.13@47.75,52.55
B2B_B0_L2_N: J2.16 JB2.23 | length 38.7
  L 01 (Top) w0.15: J2.16@20.671,68.019 20.671,67.169 20.9,66.94 21.391,66.94 22.1,66.231 22.1,65.151 27.181,60.07 45.236,60.07 50.17,55.136 ; 50.071,55.235 50.17,55.136 50.17,53.825 50.25,53.745 JB2.23@50.25,52.85 JB2.23@50.25,52.55
B2B_B0_L2_P: J2.15 JB2.21 | length 38.1
  L 01 (Top) w0.15: J2.15@20.671,65.479 20.671,66.371 20.9,66.6 21.25,66.6 21.76,66.09 21.76,65.01 27.04,59.73 45.095,59.73 49.83,54.995 49.83,53.805 49.75,53.725 JB2.21@49.75,52.85 JB2.21@49.75,52.55
B2B_B0_L3_N: J2.26 JB2.28 | length 34
  L 01 (Top) w0.15: JB2.28@51.25,48.85 51.25,50.071 51.64,50.46 v1(51.552,50.46) ; v1@51.318,50.316 cw(c51.179,50.23) 51.294,50.115 cw(c51.477,49.932) v1@51.513,50.188
  L 04 (Bot) w0.15: J2.26@33.371,68.019 33.371,67.094 33.55,66.915 33.991,66.915 34.8,66.106 34.8,61.59 37.825,58.565 47.222,58.565 51.135,54.651 51.135,50.877 ; v1@51.278,50.485 ccw(c50.787,50.528) 51.135,50.877 ; v1@51.527,50.734 cw(c51.484,51.225) 51.135,50.877 ; v1(51.552,50.46) 51.135,50.877
B2B_B0_L3_P: J2.25 JB2.26 | length 34.8
  L 01 (Top) w0.15: v1@50.458,50.258 cw(c49.752,49.552) JB2.26@50.75,49.552 ; v1@50.564,50.364 cw(c50.115,49.915) 50.75,49.915 ; v1(50.652,50.452) 50.75,50.355 JB2.26@50.75,48.85 ; 50.75,50.025 cw(c51.08,50.025) v1@50.847,50.258
  L 04 (Bot) w0.15: J2.25@33.371,65.479 33.371,66.396 33.55,66.575 33.85,66.575 34.46,65.965 34.46,61.449 37.684,58.225 47.081,58.225 50.775,54.531 v1@50.775,50.55 ; v1@50.458,50.647 ccw(c49.693,51.412) 50.775,51.412 ; v1@50.564,50.541 ccw(c50.055,51.05) 50.775,51.05 ; 50.775,50.821 ccw(c51.021,50.821) v1@50.847,50.647
B2B_B0_L4_N: J2.17 JB2.25 | length 37.3
  L 01 (Top) w0.15: J2.17@23.211,65.479 23.211,66.411 23.4,66.6 23.8,66.6 24.335,66.065 24.335,64.364 27.649,61.05 45.5,61.05 50.83,55.72 50.83,53.85 50.75,53.77 JB2.25@50.75,52.85 ; JB2.25@50.75,52.55 JB2.25@50.75,52.85
B2B_B0_L4_P: J2.18 JB2.27 | length 37.9
  L 01 (Top) w0.15: J2.18@23.211,68.019 23.211,67.129 23.4,66.94 23.941,66.94 24.675,66.206 24.675,64.505 27.79,61.39 45.641,61.39 51.17,55.861 51.17,53.85 51.25,53.77 JB2.27@51.25,52.85 JB2.27@51.25,52.55
B2B_B0_L5_N: J2.21 JB2.31 | length 33.5
  L 01 (Top) w0.15: J2.21@28.291,65.479 28.325,65.514 28.325,66.425 28.475,66.575 28.769,66.575 29.385,65.959 29.385,64.935 32.01,62.31 45.965,62.31 52.33,55.945 52.33,53.85 52.25,53.77 JB2.31@52.25,52.85 ; JB2.31@52.25,52.55 JB2.31@52.25,52.85
B2B_B0_L5_P: J2.22 JB2.33 | length 34.1
  L 01 (Top) w0.15: J2.22@28.291,68.019 28.291,67.049 28.425,66.915 28.91,66.915 29.725,66.1 29.725,65.076 32.151,62.65 46.106,62.65 52.67,56.086 52.67,53.85 52.75,53.77 JB2.33@52.75,52.85 JB2.33@52.75,52.55
B2B_B0_L6_N: J2.23 JB2.35 | length 32.5
  L 01 (Top) w0.15: J2.23@30.831,65.479 30.831,66.381 31.025,66.575 31.475,66.575 31.96,66.09 31.96,64.82 33.12,63.66 46.39,63.66 53.31,56.74 53.31,53.85 53.25,53.79 JB2.35@53.25,52.85 JB2.35@53.25,52.55
B2B_B0_L6_P: J2.24 JB2.37 | length 33.1
  L 01 (Top) w0.15: J2.24@30.831,68.019 30.831,67.109 31.025,66.915 31.616,66.915 32.3,66.231 32.3,64.961 33.261,64 46.531,64 53.65,56.881 53.65,53.825 53.75,53.725 JB2.37@53.75,52.85 JB2.37@53.75,52.55
B2B_B0_L7_N: J4.39 J11.8 JB2.42 | length 88.7
  L 01 (Top) w0.15: JB2.42@54.75,48.85 54.75,48.074 54.975,47.85 54.975,47.025 ; v1@55.102,46.658 ccw(c54.661,46.711) 54.975,47.025 ; v1@55.342,46.898 cw(c55.289,47.339) 54.975,47.025 ; v1(55.375,46.625) 54.975,47.025
  L 04 (Bot) w0.15: v1@55.375,46.575 55.685,46.265 ; v1@55.434,46.356 cw(c55.486,46.116) 55.66,46.29 cw(c55.794,46.424) v1@55.623,46.506 ; 55.685,46.259 61.434,40.51 82.141,40.51 85.981,44.35 100.731,44.35 103.231,46.85 109.606,46.85 110.575,47.819 110.575,55.306 107.79,58.091 107.79,60.884 111,64.094 111,66.15 111.45,66.6 111.95,66.6 112.111,66.439 J4.39@112.111,65.479 ; J11.8@104.13,45.78 104.13,46.82
B2B_B0_L7_P: J4.40 J11.6 JB2.44 | length 87.4
  L 01 (Top) w0.15: JB2.44@55.25,48.85 55.315,48.785 55.315,47.815 v1(55.603,47.527)
  L 04 (Bot) w0.15: v1@55.603,47.267 56.025,46.845 56.025,46.4 61.575,40.85 82,40.85 85.84,44.69 100.59,44.69 103.09,47.19 109.465,47.19 110.235,47.96 110.235,55.165 107.45,57.95 107.45,61.025 110.66,64.235 110.66,66.291 111.309,66.94 111.95,66.94 112.111,67.101 J4.40@112.111,68.019 ; v1@55.711,47.465 ccw(c55.963,47.319) 55.757,47.113 ; v1@55.841,47.389 ccw(c56.137,47.217) 55.895,46.975 ; 104.13,47.22 J11.6@104.13,48.32
B2B_B0_L8_N: J2.37 JB2.41 | length 17.9
  L 01 (Top) w0.15: J2.37@48.611,65.479 48.611,66.311 48.85,66.55 49.25,66.55 49.71,66.09 49.71,62.065 54.81,56.965 54.81,53.85 54.75,53.79 JB2.41@54.75,52.85 JB2.41@54.75,52.55
B2B_B0_L8_P: J2.38 JB2.43 | length 18.5
  L 01 (Top) w0.15: J2.38@48.611,68.019 48.611,67.129 48.85,66.89 49.391,66.89 50.05,66.231 50.05,62.206 55.15,57.106 55.15,53.85 55.25,53.75 JB2.43@55.25,52.85 JB2.43@55.25,52.55
B2B_B0_L32_N: J2.28 JB2.38 | length 34.6
  L 01 (Top) w0.15: JB2.38@53.75,48.85 53.75,50.308 v1(53.902,50.46) ; JB2.38@53.75,49.43 cw(c54.933,49.43) v1@54.097,50.266 ; JB2.38@53.75,49.792 cw(c54.57,49.792) v1@53.99,50.372
  L 04 (Bot) w0.15: J2.28@35.911,68.019 35.911,67.104 36.075,66.94 36.741,66.94 37.325,66.356 37.325,61.4 38.735,59.99 47.616,59.99 53.635,53.971 53.635,51.096 53.902,50.829 ; 53.629,51.102 cw(c53.198,50.67) v1@53.782,50.496 ; 53.807,50.924 cw(c53.472,50.589) v1@53.926,50.453
B2B_B0_L32_P: J2.27 JB2.36 | length 37.5
  L 01 (Top) w0.15: v1@52.808,50.583 cw(c51.741,49.516) JB2.36@53.25,49.516 ; v1@52.914,50.689 cw(c52.103,49.878) JB2.36@53.25,49.878 ; v1(53.003,50.777) 53.25,50.53 JB2.36@53.25,48.85 ; v1@53.02,50.795 cw(c52.465,50.24) 53.25,50.24
  L 04 (Bot) w0.15: J2.27@35.911,65.479 35.911,66.436 36.075,66.6 36.6,66.6 36.985,66.215 36.985,61.259 38.594,59.65 47.475,59.65 53.275,53.85 v1@53.275,50.975 ; v1@52.808,50.972 ccw(c51.681,52.099) 53.275,52.099 ; v1@52.914,50.866 ccw(c52.043,51.737) 53.275,51.737 ; v1@53.02,50.76 ccw(c52.405,51.375) 53.275,51.375 ; v1@53.126,50.654 ccw(c52.767,51.013) 53.275,51.013
B2B_B0_L33_N: J2.29 JB2.46 | length 33.8
  L 01 (Top) w0.15: v1(55.528,50.452) 55.75,50.23 JB2.46@55.75,49.15 ; JB2.46@55.75,48.85 55.75,49.975
  L 04 (Bot) w0.15: J2.29@38.451,65.479 38.451,66.376 38.65,66.575 39.05,66.575 39.56,66.065 39.56,62.534 41.294,60.8 48.1,60.8 55.775,53.125 v1@55.775,50.452 ; v1@55.333,50.647 ccw(c54.267,51.713) 55.775,51.713 ; v1@55.439,50.541 ccw(c54.629,51.351) 55.775,51.351 ; v1@55.545,50.435 ccw(c54.991,50.989) 55.775,50.989
B2B_B0_L33_P: J2.30 JB2.48 | length 30.7
  L 01 (Top) w0.15: JB2.48@56.25,48.85 JB2.48@56.303,48.903 ; JB2.48@56.25,49.15 56.25,50.226 v1(56.418,50.394)
  L 04 (Bot) w0.15: J2.30@38.451,68.019 38.451,67.114 38.65,66.915 39.191,66.915 39.9,66.206 39.9,62.675 41.435,61.14 48.241,61.14 56.115,53.266 56.115,50.735 v1@56.418,50.432
B2B_B0_L34_N: J2.33 JB2.45 | length 27
  L 01 (Top) w0.15: v1@55.728,54.493 cw(c55.558,54.225) 55.875,54.225 ; JB2.45@55.75,52.85 55.75,54.1 55.875,54.225 ; JB2.45@55.75,52.55 JB2.45@55.75,52.85 ; v1(55.875,54.725) 55.875,54.63 55.875,54.225 ; v1@56.022,54.493 ccw(c56.192,54.225) 55.875,54.225
  L 04 (Bot) w0.15: J2.33@43.531,65.479 43.531,66.381 43.725,66.575 43.95,66.575 44.635,65.89 44.635,63.634 46.319,61.95 49.119,61.95 55.953,55.116 ; 55.074,55.995 cw(c53.803,54.725) v1@55.6,54.725 ; 55.33,55.739 cw(c54.316,54.725) v1@55.75,54.725 ; 55.586,55.483 cw(c54.828,54.725) v1@55.9,54.725 ; 55.842,55.227 cw(c55.34,54.725) v1@56.05,54.725 ; v1@55.846,54.999 ccw(c55.834,55.116) 55.953,55.116 ; v1@55.953,54.725 55.953,55.116 ; v1@56.039,54.946 cw(c56.165,55.116) 55.953,55.116
B2B_B0_L34_P: J2.34 JB2.47 | length 24.9
  L 01 (Top) w0.15: JB2.47@56.25,52.55 JB2.47@56.25,52.85 56.25,53.8 ; v1@56.335,54.092 cw(c56.027,54.023) 56.25,53.8 ; v1@56.542,53.884 ccw(c56.473,53.577) 56.25,53.8 ; v1@56.575,54.125 56.575,54.153 v1(56.603,54.153) 56.25,53.8
  L 04 (Bot) w0.15: J2.34@43.531,68.019 43.531,67.109 43.725,66.915 44.091,66.915 44.975,66.031 44.975,63.775 46.46,62.29 49.26,62.29 56.575,54.975 v1@56.575,54.153 ; v1@56.408,54.347 ccw(c56.006,54.75) 56.575,54.75 ; 56.575,54.521 ccw(c56.972,54.521) v1@56.691,54.241 ; 56.575,54.884 ccw(c57.334,54.884) v1@56.797,54.347
B2B_B0_L35_N: J2.39 JB2.51 | length 18.8
  L 01 (Top) w0.15: J2.39@51.151,65.479 51.151,66.376 51.4,66.625 53.65,66.625 57.31,62.965 57.31,53.85 57.25,53.79 JB2.51@57.25,52.85
B2B_B0_L35_P: J2.40 JB2.53 | length 19.6
  L 01 (Top) w0.15: J2.40@51.151,68.019 51.151,67.214 51.4,66.965 53.791,66.965 57.65,63.106 57.65,53.85 57.75,53.75 JB2.53@57.75,52.85 JB2.53@57.75,52.55
B2B_B0_L36_N: J4.38 J12.3 JB2.54 | length 84.7
  L 01 (Top) w0.15: 57.75,48.077 ccw(c58.552,48.077) v1@57.985,47.51 ; JB2.54@57.75,48.439 ccw(c58.914,48.439) v1@58.091,47.616 ; JB2.54@57.75,48.801 ccw(c59.277,48.801) v1@58.197,47.722 ; JB2.54@57.75,48.85 57.75,47.675 57.975,47.45 58.003,47.478 v1(58.003,47.527)
  L 04 (Bot) w0.15: v1@58.003,47.252 cw(c58.003,46.588) 58.472,47.058 cw(c58.942,47.527) v1@58.278,47.527 ; v1(58.003,47.527) 58.49,47.04 58.49,45.816 62.256,42.05 80.95,42.05 86.14,47.24 96.475,47.24 ; J12.3@96.5,48.32 96.5,47.265 96.475,47.24 ; J4.38@109.571,68.019 109.571,67.136 109.35,66.915 108.759,66.915 108.175,66.331 108.175,63.806 106.15,61.781 106.15,57.369 109.125,54.394 109.125,50.25 108.59,49.715 103.09,49.715 100.615,47.24 96.475,47.24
